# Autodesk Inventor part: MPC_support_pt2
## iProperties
Shininess: 64.0
Length Units: 11272
Angle Units: 11279
Time Units: 11290
Mass Units: 11286
Length Display Precision: 3
Angle Display Precision: 2
Compacted: True
Part Number: MPC_support_pt2
Document SubType Name: Modeling
Created: 2004-08
Designer: John Blackburn
Manufacturer: Standard
Standards Organization: Custom
Density: 0.0
Volumn: 0.0
Area: 0.0
PropertySet Name: Model Information
Control State: 0
Master: False
Checked Out: False
Author: John Blackburn
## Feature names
1. Base1
2. Hole1
